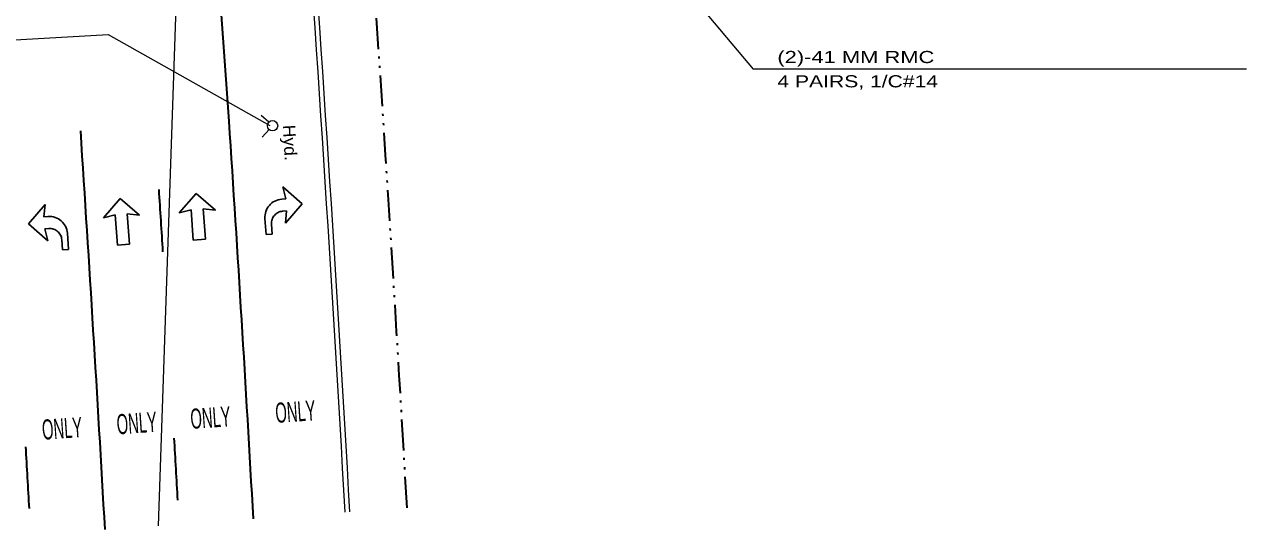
# Model space of a CAD drawing. Extents: x 168203 to 169863, y 223196 to 223870.
# Drawn here: x 168359.5 to 168418.6, y 223554.6 to 223579 of the extents above; entities that cross this region are included whole.
import ezdxf
from ezdxf.enums import TextEntityAlignment as Align

# ---------------------------------------------------------------- set-up
doc = ezdxf.new("R2010")
doc.units = 0
doc.header["$LTSCALE"] = 0.3
doc.linetypes.add('DASH_DOUBLE_DOT', pattern=[9.2, 5, -1.2, 0.3, -1.2, 0.3, -1.2])
doc.linetypes.add('LONG_DASH_SHORT_DASH', pattern=[9.9, 6, -1.2, 1.5, -1.2])
for name, color, linetype, lineweight in [('1', 7, 'Continuous', 13), ('23', 7, 'Continuous', 25), ('36', 7, 'Continuous', 35), ('9', 7, 'Continuous', 13)]:
    doc.layers.add(name, color=color, linetype=linetype, lineweight=lineweight)

msp = doc.modelspace()

# ---------------------------------------------------------------- linework, layer by layer
at = {"layer": '1'}
for radius, start in [(2218.9, 3.25121), (2219.13, 3.2513)]:
    msp.add_arc((166159.6759, 223429.5469), radius, start, 4.13349, dxfattribs=at)
at = {"layer": '1', "linetype": 'DASH_DOUBLE_DOT', "lineweight": 35}
msp.add_arc((166159.6764, 223429.5467), 2221.9, 3.2524, 4.13349, dxfattribs=at)
at = {"layer": '23', "lineweight": 13}
for p, q in [((168367.4305, 223597.8004), (168365.9593, 223554.7364)), ((168353.5788, 223577.9352), (168363.5377, 223578.5022)), ((168363.5377, 223578.5022), (168371.3602, 223574.0988)), ((168371.304, 223574.2568), (168370.932, 223574.5907)), ((168371.3232, 223573.9037), (168370.9892, 223573.5317))]:
    msp.add_line(p, q, dxfattribs=at)
msp.add_circle((168371.4901, 223574.0898), 0.25, dxfattribs=at)
at = {"layer": '36'}
msp.add_line((168369.3895, 223574.3146), (168366.6354, 223612.4238), dxfattribs=at)
at = {"layer": '36', "linetype": 'LONG_DASH_SHORT_DASH', "lineweight": 25}
for points in [[(168371.9356, 223570.5384), (168372.1302, 223570.5525), (168371.9908, 223571.1291), (168372.9296, 223570.3169), (168372.1174, 223569.3781), (168372.1724, 223569.9688), (168371.9778, 223569.9547)], [(168360.6642, 223569.1152), (168360.4696, 223569.1011), (168360.609, 223568.5245), (168359.6702, 223569.3367), (168360.4824, 223570.2755), (168360.4274, 223569.6848), (168360.622, 223569.6989)], [(168371.4363, 223569.3289), (168371.4715, 223568.8424), (168371.1797, 223568.8214), (168371.1234, 223569.5996)], [(168361.5608, 223568.8866), (168361.617, 223568.1084), (168361.3252, 223568.0873), (168361.29, 223568.5737)]]:
    msp.add_lwpolyline(points, dxfattribs=at)
for points in [[(168363.3011, 223569.6383), (168364.1133, 223570.5771), (168365.0521, 223569.7649), (168364.4614, 223569.8199), (168364.5669, 223568.3607), (168363.9832, 223568.3185), (168363.8777, 223569.7777)], [(168366.9737, 223569.8797), (168367.7859, 223570.8185), (168368.7247, 223570.0063), (168368.134, 223570.0613), (168368.2395, 223568.6021), (168367.6558, 223568.5599), (168367.5503, 223570.0191)]]:
    msp.add_lwpolyline(points, close=True, dxfattribs=at)
at = {"layer": '36'}
for radius, start, end in [(2214.4501, 3.24946, 3.74834), (2207.2499, 3.24659, 3.74834), (2210.8499, 3.59029, 3.66829), (2210.8499, 3.27828, 3.35628), (2203.6498, 3.27829, 3.35628)]:
    msp.add_arc((166159.6765, 223429.5465), radius, start, end, dxfattribs=at)
at = {"layer": '36', "linetype": 'LONG_DASH_SHORT_DASH', "lineweight": 25}
for centre, radius, start, end in [((168371.999, 223569.6629), 0.8778, 94.13419, 184.13419), ((168372.0201, 223569.371), 0.5852, 94.13419, 184.13419), ((168360.6852, 223568.8233), 0.8778, 4.13419, 94.13419), ((168360.7063, 223568.5315), 0.5852, 4.13419, 94.13419)]:
    msp.add_arc(centre, radius, start, end, dxfattribs=at)
at = {"layer": '9'}
for p in [(168372.3015, 223603.4006), (168418.6318, 223576.8324)]:
    msp.add_line(p, (168394.7583, 223576.8324), dxfattribs=at)

# ---------------------------------------------------------------- texts
at = {"layer": '23', "width": 1.05}
msp.add_text('Hyd.', height=0.6, rotation=273.098, dxfattribs=at).set_placement((168371.9893, 223574.1168))
at = {"layer": '36', "width": 0.55}
for p in [(168368.5186, 223559.4847), (168372.6296, 223559.7748), (168361.3361, 223558.9606), (168364.9499, 223559.2184)]:
    msp.add_text('ONLY', height=0.9715, rotation=3.898, dxfattribs=at).set_placement(p, align=Align.CENTER)
at = {"layer": '9'}
for s, width, p in [('(2)-41 MM RMC                        ', 1.35, (168395.924, 223577.1216)), ('4 PAIRS, 1/C#14                      ', 1.3, (168395.924, 223575.9469))]:
    msp.add_text(s, height=0.5873, dxfattribs=dict(at, width=width)).set_placement(p)

doc.saveas('drawing.dxf')
